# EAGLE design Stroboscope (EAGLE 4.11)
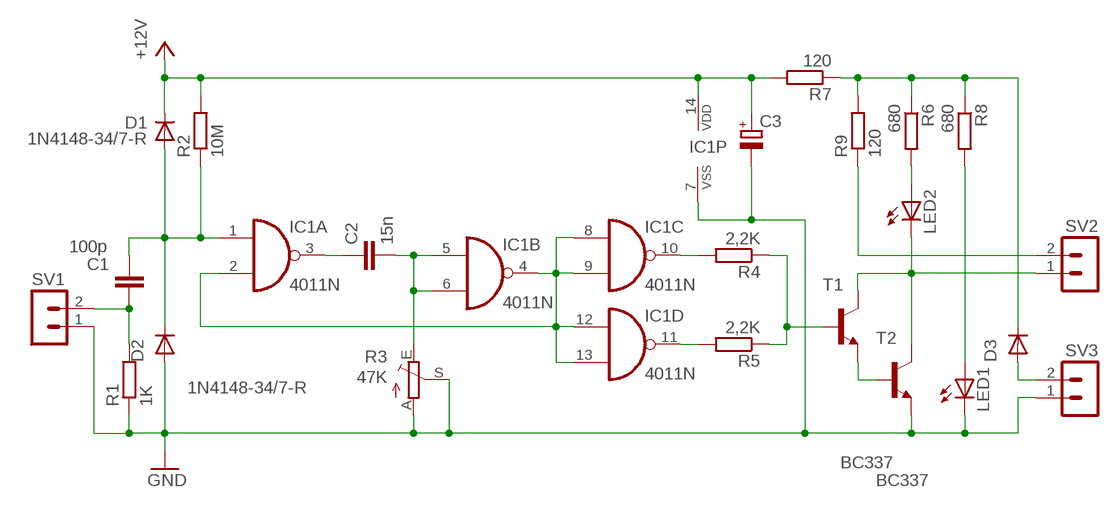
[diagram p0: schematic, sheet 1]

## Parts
C1  100p  C-EU_C050  [C050-025X075]
C2  15n  C-EU_C050  [C050-025X075]
C3  CPOL-EUE5-10.5  [E5-10,5]
D1  1N4148-34/7-R  [D-7,5/R]
D2  1N4148-34/7-R  [D-7,5/R]
D3  1N4001/7MM-R  [DO34-7/R]
IC1  4011N  [DIL14]
LED1  LED  [LED3MM]
LED2  LED  [LED3MM]
R1  1K  R-EU_207  [0207/10]
R2  10M  R-EU_207  [0207/10]
R3  47K  TRIM_EU-CA14H  [CA14H]
R4  2,2K  R-EU_207  [0207/10]
R5  2,2K  R-EU_207  [0207/10]
R6  680  R-EU_207  [0207/10]
R7  120  R-EU_207  [0207/10]
R8  680  R-EU_207  [0207/10]
R9  120  R-EU_207  [0207/10]
SV1  MA2-1  [MA2-1]
SV2  MA2-1  [MA2-1]
SV3  MA2-1  [MA2-1]
T1  BC337  [TO92-]
T2  BC337  [TO92-]

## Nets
GND: C3.- D2.A IC1.7(P:VSS) LED1.K(C) R1.1 R3.A R3.S SV1.1 SV3.1 T2.1(E)
N$1: C1.P$1 R1.2 SV1.2
N$2: C1.P$2 D1.A D2.C IC1.1(A:I0) R2.1
N$4: C2.P$1 IC1.3(A:O)
N$5: C2.P$2 IC1.5(B:I0) IC1.6(B:I1) R3.E
N$8: IC1.2(A:I1) IC1.4(B:O) IC1.8(C:I0) IC1.9(C:I1) IC1.12(D:I0) IC1.13(D:I1)
N$9: T1.1(E) T2.2(B)
N$10: LED2.A R6.2
N$11: LED2.K(C) SV2.1 T1.3(C) T2.3(C)
N$12: IC1.10(C:O) R4.2
N$13: IC1.11(D:O) R5.2
N$14: R4.1 R5.1 T1.2(B)
N$15: LED1.A R8.2
N$16: R9.1 SV2.2
N$17: D3.A SV3.2
N$18: D3.C R6.1 R7.1 R8.1 R9.2
VCC: C3.+ D1.C IC1.14(P:VDD) R2.2 R7.2 ; supply symbol labelled +12V

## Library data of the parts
C1 C2 = 2gab:C-EU_
C3 = rcl:CPOL-EU: POLARIZED CAPACITOR, European symbol
D1 D2 = 2gab:1N4148: DIODE
D3 = 2gab:1N4001: DIODE
IC1 = 40xx:4011: Quad 2-input NAND
LED1 LED2 = 2gab:LED
R1 R2 R4-R9 = 2gab:R-EU_
R3 = pot:TRIM_EU-: POTENTIOMETER
SV1-SV3 = 2gab:MA2-1
T1 T2 = 2gab:BC337

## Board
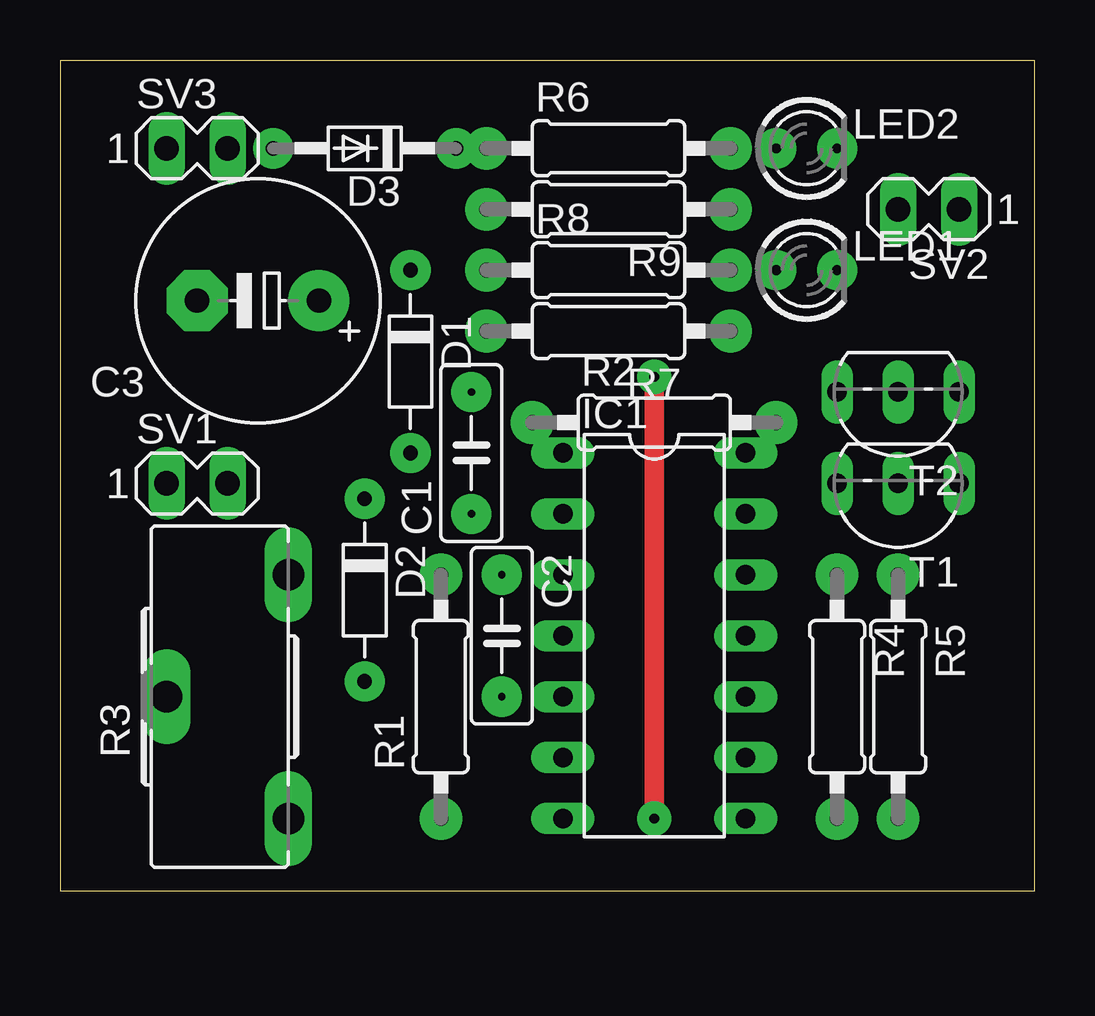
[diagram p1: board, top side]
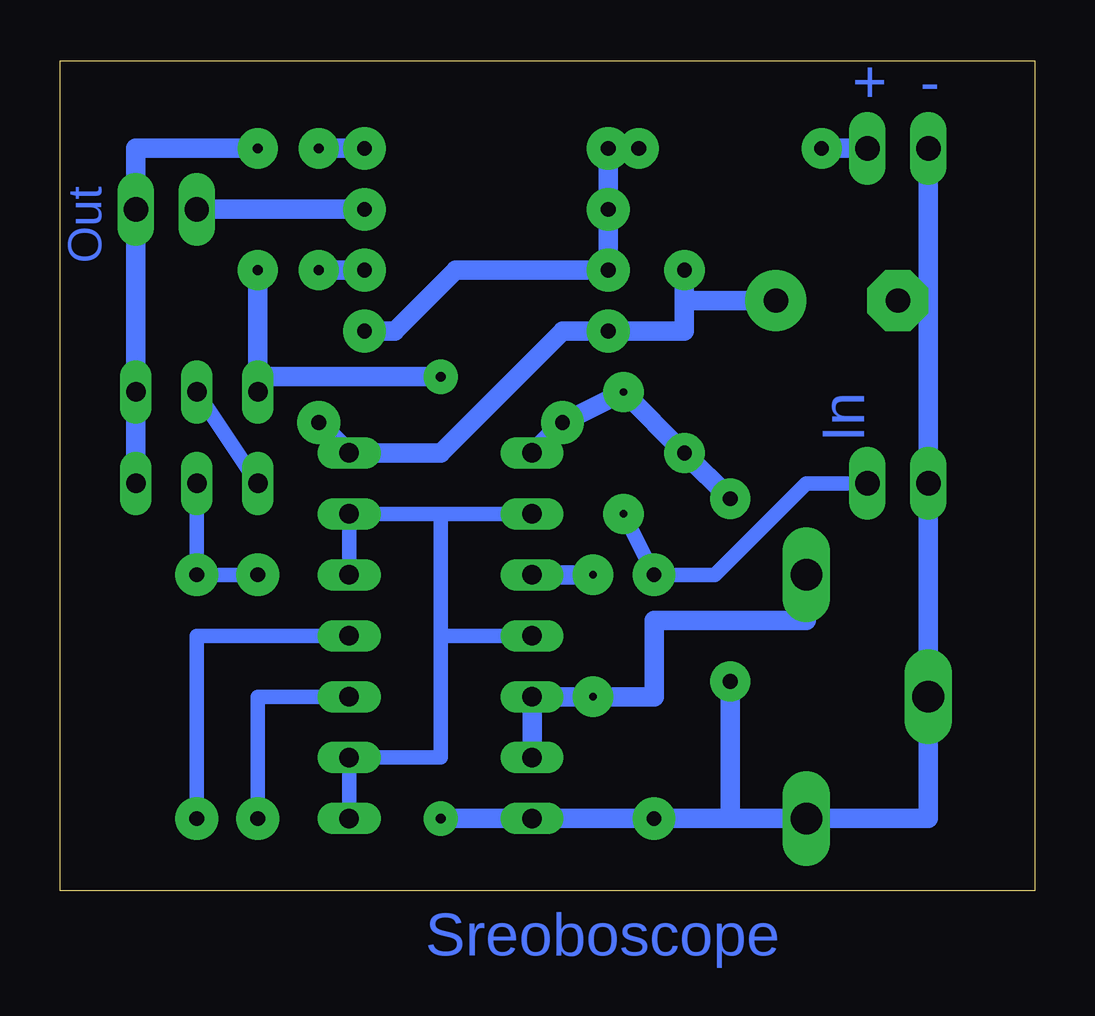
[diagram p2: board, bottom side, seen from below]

Size 40.62 x 34.59 mm. Coordinates in mm from the lower left corner, seen from the top.
Outline: 0,0 40.62,0 40.62,34.59 0,34.59 0,0
Copper layers (1*16): Top 0.035mm / dielectric 1.5mm / Bottom 0.035mm
Design rules "Hobby 2": minimum track width 10mil, minimum drill 10mil, track to track 16mil, track to pad 16mil, pad to pad 16mil, via to via 16mil, smd to smd 8mil, copper to edge 40mil, drill to drill 8mil, minimum pad ring 10mil, minimum via ring 8mil, stop-mask expansion 4mil, vias tented up to drill 0mil, thermal gap 10mil

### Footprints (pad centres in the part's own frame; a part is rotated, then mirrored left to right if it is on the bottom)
C050-025X075 = drill 0.305 pad 1.676 round: P$1 -2.54,0; P$2 2.54,0
E5-10,5 = drill 1.016 pad 2.54 round: + -2.54,0 | drill 1.016 pad 2.54 octagon: - 2.54,0
D-7,5/R = drill 0.61 pad 1.676 round: A 3.81,0; C -3.81,0
DO34-7/R = drill 0.61 pad 1.676 round: A 3.81,0; C -3.81,0
DIL14 = drill 0.813 long: 1 -7.62,-3.81; 2 -5.08,-3.81; 3 -2.54,-3.81; 4 0,-3.81; 5 2.54,-3.81; 6 5.08,-3.81; 7 7.62,-3.81; 8 7.62,3.81; 9 5.08,3.81; 10 2.54,3.81; 11 0,3.81; 12 -2.54,3.81; 13 -5.08,3.81; 14 -7.62,3.81
LED3MM = drill 0.406 pad 1.676 round: A -1.27,0; K 1.27,0
0207/10 = drill 0.61 pad 1.778 round: 1 -5.08,0; 2 5.08,0
CA14H = drill 1.321 long: A -5.08,0; E 5.08,0; S 0,5.08
MA2-1 = drill 1.016 long: 1 0,0; 2 2.54,0
TO92- = drill 0.813 long: 1 2.54,-1.27; 2 0,-1.27; 3 -2.54,-1.27

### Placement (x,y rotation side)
C1  17.14,18.25 90 top
C2  18.41,10.63 270 top
C3  8.25,24.6 180 top
D1  14.6,22.06 270 top
D2  12.69,12.54 270 top
D3  12.69,30.95 180 top
IC1  24.76,10.63 270 top
LED1  31.11,25.87 0 top
LED2  31.11,30.95 0 top
R1  15.87,8.09 90 top
R2  24.76,19.52 0 top
R3  9.52,8.09 90 top
R4  32.38,8.09 270 top
R5  34.92,8.09 270 top
R6  22.86,30.95 0 top
R7  22.86,23.33 180 top
R8  22.86,25.87 0 top
R9  22.86,28.41 180 top
SV1  4.44,16.98 0 top
SV2  37.46,28.41 180 top
SV3  4.44,30.95 0 top
T1  34.92,15.71 180 top
T2  34.92,19.52 180 top

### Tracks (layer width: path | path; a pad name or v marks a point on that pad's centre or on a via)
GND  (via drill 0.41 pad 1.42)
  Top 0.813: v24.76,3.01 v24.76,21.43
  Bottom 0.813: 4.44,24.6 SV3.1 | 4.44,24.6 C3.- | 12.06,3.01 R3.A 4.44,3.01 R3.S SV1.1 4.44,24.6 | 12.06,3.01 R1.1 IC1.7 v24.76,3.01 | D2.A 12.69,3.01 12.06,3.01 | v24.76,21.43 32.38,21.43 T2.1 LED1.K
N$1
  Bottom 0.61: SV1.2 9.52,16.98 13.33,13.17 R1.2 C1.P$1
N$2
  Bottom 0.813: IC1.1 R2.1 C1.P$2 D1.A D2.C
N$4
  Bottom 0.813: C2.P$1 IC1.3
N$5
  Bottom 0.813: IC1.6 IC1.5 C2.P$2 15.87,8.09 15.87,11.27 9.52,11.27 R3.E
N$8
  Bottom 0.61: 24.76,10.63 IC1.4 | IC1.8 IC1.9 24.76,5.55 24.76,10.63 | IC1.12 IC1.13 24.76,15.71 | 24.76,15.71 IC1.2 | 24.76,10.63 24.76,15.71
N$9
  Bottom 0.61: T1.1 T2.2
N$10
  Bottom 0.813: R6.2 LED2.A
N$11
  Bottom 0.813: LED2.K 37.46,30.95 SV2.1 T2.3 T1.3
N$12
  Bottom 0.61: IC1.10 32.38,8.09 R4.2
N$13
  Bottom 0.61: IC1.11 34.92,10.63 R5.2
N$14
  Bottom 0.61: T1.2 R5.1 R4.1
N$15
  Bottom 0.813: R8.2 LED1.A
N$16
  Bottom 0.813: R9.1 SV2.2
N$17
  Bottom 0.813: SV3.2 D3.A
N$18
  Bottom 0.813: D3.C R6.1 R9.2 R8.1 24.12,25.87 26.67,23.33 R7.1
VCC
  Bottom 0.813: C3.+ 14.6,24.6 | 14.6,24.6 D1.C | 14.6,24.6 14.6,23.33 R7.2 19.68,23.33 24.76,18.25 IC1.14 R2.2

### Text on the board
Bottom: + - | Out | In | Sreoboscope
